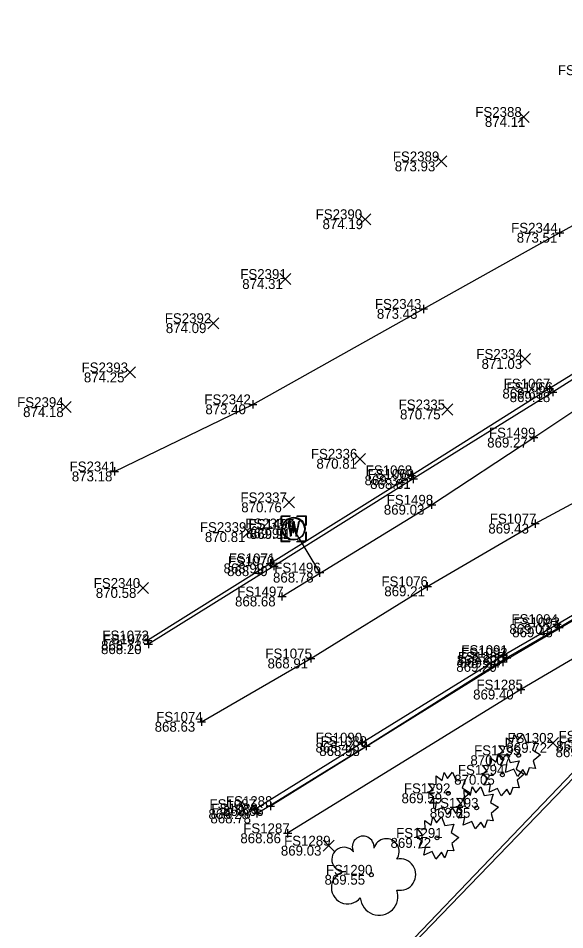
# Model space of a CAD drawing. Extents: x 1479420 to 1479833, y 379731 to 380103.
# Drawn here: x 1479419.6 to 1479485.7, y 379796.9 to 379907.1 of the extents above; entities that cross this region are included whole.
import ezdxf

# ---------------------------------------------------------------- set-up
doc = ezdxf.new("R2010")
doc.units = 0
for name, color, linetype in [('PV_X_COP', 7, 'Continuous'), ('PV_X_Curb', 7, 'Continuous'), ('PV_X_Walk', 7, 'Continuous'), ('SV_X_Break_Lines', 7, 'Continuous'), ('SV_X_Random_Point', 7, 'Continuous'), ('SV_X_Shot_Marker', 7, 'Continuous'), ('SV_X_Text_Elevation', 7, 'Continuous'), ('SV_X_Text_Name', 7, 'Continuous'), ('UT_X_Water', 7, 'Continuous'), ('UT_X_Water_Cells', 7, 'Continuous'), ('VG_X_Cells', 7, 'Continuous')]:
    doc.layers.add(name, color=color, linetype=linetype)

msp = doc.modelspace()

# ---------------------------------------------------------------- linework, layer by layer
at = {"layer": 'PV_X_COP'}
msp.add_lwpolyline([(1479441.79, 379822.02), (1479455, 379829.68), (1479469.1, 379838.41), (1479482.14, 379846), (1479493.53, 379852.15), (1479505.23, 379858.04), (1479517.8, 379863.73), (1479530.74, 379869.52), (1479544.65, 379875.38), (1479558.93, 379881.46), (1479574.04, 379887.9), (1479589.2, 379894.6), (1479596.44, 379897.36)], dxfattribs=at)
at = {"layer": 'PV_X_Curb'}
for points in [[(1479566.95, 379909.06), (1479563.85, 379905.52), (1479559.69, 379902.15), (1479555.35, 379899.31), (1479545.42, 379894.6), (1479534.9, 379889.66), (1479522.4, 379883.6), (1479509.98, 379877.66), (1479501.21, 379872.62), (1479492.67, 379867.77), (1479483.86, 379862.33), (1479467.17, 379851.84), (1479450.13, 379841.19), (1479435.27, 379831.86)], [(1479567.17, 379908.64), (1479563.94, 379905), (1479559.95, 379901.76), (1479555.61, 379898.81), (1479545.71, 379894.1), (1479535.14, 379889.11), (1479522.8, 379883.21), (1479510.32, 379877.21), (1479501.52, 379872.22), (1479492.73, 379867.27), (1479484.26, 379861.9), (1479467.4, 379851.4), (1479450.55, 379840.85), (1479435.37, 379831.41)], [(1479448.26, 379811.45), (1479461.22, 379819.5), (1479478.3, 379830.09), (1479484.79, 379833.84), (1479492.12, 379838.16), (1479500.7, 379842.97), (1479508.92, 379847.12), (1479516.09, 379849.63), (1479529.03, 379853.07), (1479547.64, 379857.82), (1479566.74, 379862.68), (1479585.84, 379867.63), (1479595.94, 379870.21)], [(1479448.5, 379810.93), (1479461.7, 379819.08), (1479478.68, 379829.77), (1479485.03, 379833.45), (1479492.45, 379837.86), (1479500.92, 379842.63), (1479509.09, 379846.69), (1479516.12, 379849.21), (1479529.31, 379852.68), (1479547.62, 379857.33), (1479567.19, 379862.3), (1479585.96, 379867.1), (1479596.07, 379869.8)], [(1479601.32, 379856.89), (1479590.52, 379858.04), (1479580.72, 379858.06), (1479571.15, 379856.79), (1479561.29, 379853.75), (1479553.09, 379850.7), (1479544.73, 379845.63), (1479537.42, 379839.85), (1479530.35, 379833.14), (1479518.15, 379820.18), (1479506.75, 379808.8), (1479505.04, 379808.13), (1479502.74, 379808.99), (1479490.36, 379819.72), (1479452.91, 379780.6)], [(1479601.35, 379856.37), (1479590.36, 379857.44), (1479580.92, 379857.48), (1479571.06, 379856.27), (1479561.56, 379853.27), (1479553.28, 379850.19), (1479545.2, 379845.23), (1479537.87, 379839.39), (1479530.79, 379832.84), (1479518.52, 379819.83), (1479508.59, 379809.05), (1479504.77, 379807.6), (1479502.38, 379808.45), (1479490.37, 379818.94), (1479453.51, 379780.8)]]:
    msp.add_lwpolyline(points, dxfattribs=at)
at = {"layer": 'PV_X_Walk'}
for points in [[(1479600.53, 379870.64), (1479580.73, 379865.6), (1479561.55, 379860.77), (1479542.71, 379855.92), (1479519.92, 379850.15), (1479513.47, 379848.18), (1479509.19, 379846.57), (1479504.25, 379844.07), (1479496.36, 379839.93), (1479478.25, 379829.27), (1479450.13, 379811.82)], [(1479601.31, 379866.86), (1479581.55, 379861.92), (1479562.5, 379857.02), (1479543.7, 379852.15), (1479520.94, 379846.41), (1479515.03, 379844.63), (1479510.75, 379842.94), (1479506.29, 379840.86), (1479498.37, 379836.48), (1479480.41, 379825.92), (1479452.2, 379808.53)]]:
    msp.add_lwpolyline(points, dxfattribs=at)
at = {"layer": 'SV_X_Break_Lines'}
msp.add_lwpolyline([(1479431.27, 379852.31), (1479448, 379860.43), (1479468.63, 379871.98), (1479485.1, 379881.19), (1479495.91, 379887.13), (1479497.06, 379892.33), (1479500.76, 379896.46), (1479508.23, 379894.89), (1479514.09, 379896.92), (1479525.63, 379901.77), (1479534.39, 379905.65), (1479543.52, 379912.47)], dxfattribs=at)
at = {"layer": 'SV_X_Random_Point'}
for p, q in [((1479480.1, 379894.54), (1479481.43, 379895.87)), ((1479480.1, 379895.87), (1479481.43, 379894.54)), ((1479470.13, 379889.16), (1479471.47, 379890.49)), ((1479470.13, 379890.49), (1479471.47, 379889.16)), ((1479460.91, 379882.16), (1479462.25, 379883.49)), ((1479460.91, 379883.49), (1479462.25, 379882.16)), ((1479451.25, 379874.92), (1479452.58, 379876.26)), ((1479451.25, 379876.26), (1479452.58, 379874.92)), ((1479442.55, 379869.58), (1479443.88, 379870.91)), ((1479442.55, 379870.91), (1479443.88, 379869.58)), ((1479480.23, 379865.25), (1479481.57, 379866.58)), ((1479480.23, 379866.58), (1479481.57, 379865.25)), ((1479432.5, 379863.63), (1479433.83, 379864.96)), ((1479432.5, 379864.96), (1479433.83, 379863.63)), ((1479424.7, 379859.43), (1479426.03, 379860.76)), ((1479424.7, 379860.76), (1479426.03, 379859.43)), ((1479470.84, 379859.14), (1479472.17, 379860.48)), ((1479470.84, 379860.48), (1479472.17, 379859.14)), ((1479460.31, 379853.17), (1479461.64, 379854.5)), ((1479460.31, 379854.5), (1479461.64, 379853.17)), ((1479451.71, 379847.91), (1479453.04, 379849.24)), ((1479451.71, 379849.24), (1479453.04, 379847.91)), ((1479446.82, 379844.3), (1479448.15, 379845.64)), ((1479446.82, 379845.64), (1479448.15, 379844.3)), ((1479434.07, 379837.54), (1479435.4, 379838.88)), ((1479434.07, 379838.88), (1479435.4, 379837.54)), ((1479483.63, 379818.8), (1479484.96, 379820.14)), ((1479483.63, 379820.14), (1479484.96, 379818.8)), ((1479456.49, 379806.36), (1479457.83, 379807.7)), ((1479456.49, 379807.7), (1479457.83, 379806.36))]:
    msp.add_line(p, q, dxfattribs=at)
at = {"layer": 'SV_X_Shot_Marker'}
for p, q in [((1479484.6, 379881.19), (1479485.6, 379881.19)), ((1479485.1, 379881.69), (1479485.1, 379880.69)), ((1479485.1, 379881.19), (1479485.1, 379881.19)), ((1479468.63, 379872.48), (1479468.63, 379871.48)), ((1479468.13, 379871.98), (1479469.13, 379871.98)), ((1479468.63, 379871.98), (1479468.63, 379871.98)), ((1479483.36, 379862.33), (1479484.36, 379862.33)), ((1479483.86, 379862.83), (1479483.86, 379861.83)), ((1479483.86, 379862.33), (1479483.86, 379862.33)), ((1479484.26, 379862.4), (1479484.26, 379861.4)), ((1479483.76, 379861.9), (1479484.76, 379861.9)), ((1479484.26, 379861.9), (1479484.26, 379861.9)), ((1479447.5, 379860.43), (1479448.5, 379860.43)), ((1479448, 379860.93), (1479448, 379859.93)), ((1479448, 379860.43), (1479448, 379860.43)), ((1479481.98, 379856.9), (1479481.98, 379855.9)), ((1479481.48, 379856.4), (1479482.48, 379856.4)), ((1479481.98, 379856.4), (1479481.98, 379856.4)), ((1479430.77, 379852.31), (1479431.77, 379852.31)), ((1479431.27, 379852.81), (1479431.27, 379851.81)), ((1479431.27, 379852.31), (1479431.27, 379852.31)), ((1479467.17, 379852.34), (1479467.17, 379851.34)), ((1479466.67, 379851.84), (1479467.67, 379851.84)), ((1479466.9, 379851.4), (1479467.9, 379851.4)), ((1479467.17, 379851.84), (1479467.17, 379851.84)), ((1479467.4, 379851.9), (1479467.4, 379850.9)), ((1479467.4, 379851.4), (1479467.4, 379851.4)), ((1479469.11, 379848.28), (1479470.11, 379848.28)), ((1479469.61, 379848.78), (1479469.61, 379847.78)), ((1479469.61, 379848.28), (1479469.61, 379848.28)), ((1479452.88, 379845.86), (1479452.88, 379844.86)), ((1479481.64, 379846), (1479482.64, 379846)), ((1479482.14, 379846.5), (1479482.14, 379845.5)), ((1479482.14, 379846), (1479482.14, 379846)), ((1479452.38, 379845.36), (1479453.38, 379845.36)), ((1479452.88, 379845.36), (1479452.88, 379845.36)), ((1479449.63, 379841.19), (1479450.63, 379841.19)), ((1479450.13, 379841.69), (1479450.13, 379840.69)), ((1479450.13, 379841.19), (1479450.13, 379841.19)), ((1479450.55, 379841.35), (1479450.55, 379840.35)), ((1479450.05, 379840.85), (1479451.05, 379840.85)), ((1479450.55, 379840.85), (1479450.55, 379840.85)), ((1479455.57, 379840.07), (1479456.57, 379840.07)), ((1479456.07, 379840.57), (1479456.07, 379839.57)), ((1479456.07, 379840.07), (1479456.07, 379840.07)), ((1479469.1, 379838.91), (1479469.1, 379837.91)), ((1479468.6, 379838.41), (1479469.6, 379838.41)), ((1479469.1, 379838.41), (1479469.1, 379838.41)), ((1479451.02, 379837.18), (1479452.02, 379837.18)), ((1479451.52, 379837.68), (1479451.52, 379836.68)), ((1479451.52, 379837.18), (1479451.52, 379837.18)), ((1479484.29, 379833.84), (1479485.29, 379833.84)), ((1479484.53, 379833.45), (1479485.53, 379833.45)), ((1479484.79, 379834.34), (1479484.79, 379833.34)), ((1479484.79, 379833.84), (1479484.79, 379833.84)), ((1479485.03, 379833.95), (1479485.03, 379832.95)), ((1479485.03, 379833.45), (1479485.03, 379833.45)), ((1479435.27, 379832.36), (1479435.27, 379831.36)), ((1479434.77, 379831.86), (1479435.77, 379831.86)), ((1479434.87, 379831.41), (1479435.87, 379831.41)), ((1479435.27, 379831.86), (1479435.27, 379831.86)), ((1479435.37, 379831.91), (1479435.37, 379830.91)), ((1479435.37, 379831.41), (1479435.37, 379831.41)), ((1479455, 379830.18), (1479455, 379829.18)), ((1479477.8, 379830.09), (1479478.8, 379830.09)), ((1479478.3, 379830.59), (1479478.3, 379829.59)), ((1479478.3, 379830.09), (1479478.3, 379830.09)), ((1479478.68, 379830.27), (1479478.68, 379829.27)), ((1479454.5, 379829.68), (1479455.5, 379829.68)), ((1479455, 379829.68), (1479455, 379829.68)), ((1479477.75, 379829.27), (1479478.75, 379829.27)), ((1479478.18, 379829.77), (1479479.18, 379829.77)), ((1479478.25, 379829.77), (1479478.25, 379828.77)), ((1479478.25, 379829.27), (1479478.25, 379829.27)), ((1479478.68, 379829.77), (1479478.68, 379829.77)), ((1479479.91, 379825.92), (1479480.91, 379825.92)), ((1479480.41, 379826.42), (1479480.41, 379825.42)), ((1479480.41, 379825.92), (1479480.41, 379825.92)), ((1479441.79, 379822.52), (1479441.79, 379821.52)), ((1479441.29, 379822.02), (1479442.29, 379822.02)), ((1479441.79, 379822.02), (1479441.79, 379822.02)), ((1479460.72, 379819.5), (1479461.72, 379819.5)), ((1479461.2, 379819.08), (1479462.2, 379819.08)), ((1479461.22, 379820), (1479461.22, 379819)), ((1479461.22, 379819.5), (1479461.22, 379819.5)), ((1479461.7, 379819.58), (1479461.7, 379818.58)), ((1479461.7, 379819.08), (1479461.7, 379819.08)), ((1479447.76, 379811.45), (1479448.76, 379811.45)), ((1479448.26, 379811.95), (1479448.26, 379810.95)), ((1479448.26, 379811.45), (1479448.26, 379811.45)), ((1479448.5, 379811.43), (1479448.5, 379810.43)), ((1479449.63, 379811.82), (1479450.63, 379811.82)), ((1479450.13, 379812.32), (1479450.13, 379811.32)), ((1479450.13, 379811.82), (1479450.13, 379811.82)), ((1479448, 379810.93), (1479449, 379810.93)), ((1479448.5, 379810.93), (1479448.5, 379810.93)), ((1479451.7, 379808.53), (1479452.7, 379808.53)), ((1479452.2, 379809.03), (1479452.2, 379808.03)), ((1479452.2, 379808.53), (1479452.2, 379808.53))]:
    msp.add_line(p, q, dxfattribs=at)
at = {"layer": 'UT_X_Water'}
msp.add_line((1479452.88, 379845.36), (1479456.07, 379840.07), dxfattribs=at)
msp.add_lwpolyline([(1479451.52, 379837.18), (1479469.61, 379848.28), (1479481.98, 379856.4), (1479496.24, 379865.93), (1479520, 379881.31), (1479538.56, 379893), (1479553.44, 379903.41), (1479554.94, 379904.33), (1479564.84, 379911.31), (1479573.24, 379917), (1479582.4, 379926.47), (1479585.51, 379929.79), (1479589.65, 379934.74), (1479591.4, 379936.45), (1479593.77, 379939.33)], dxfattribs=at)
at = {"layer": 'UT_X_Water_Cells'}
for p, q in [((1479452.89, 379845.34), (1479452.89, 379845.34)), ((1479452.97, 379845.41), (1479452.97, 379845.41))]:
    msp.add_line(p, q, dxfattribs=at)
for points in [[(1479452.49, 379846.84), (1479451.39, 379846.84), (1479451.39, 379845.74)], [(1479452.57, 379846.91), (1479451.47, 379846.91), (1479451.47, 379845.81)], [(1479454.39, 379845.74), (1479454.39, 379846.84), (1479453.29, 379846.84)], [(1479454.47, 379845.81), (1479454.47, 379846.91), (1479453.37, 379846.91)], [(1479452.23, 379846.24), (1479452.56, 379844.44), (1479452.89, 379846.24), (1479453.23, 379844.44), (1479453.56, 379846.24)], [(1479452.3, 379846.31), (1479452.64, 379844.51), (1479452.97, 379846.31), (1479453.3, 379844.51), (1479453.64, 379846.31)], [(1479451.39, 379844.94), (1479451.39, 379843.84), (1479452.49, 379843.84)], [(1479451.47, 379845.01), (1479451.47, 379843.91), (1479452.57, 379843.91)], [(1479453.29, 379843.84), (1479454.39, 379843.84), (1479454.39, 379844.94)], [(1479453.37, 379843.91), (1479454.47, 379843.91), (1479454.47, 379845.01)]]:
    msp.add_lwpolyline(points, dxfattribs=at)
for centre in [(1479452.89, 379845.34), (1479452.97, 379845.41)]:
    msp.add_circle(centre, 1.35, dxfattribs=at)
at = {"layer": 'VG_X_Cells'}
for points in [[(1479480.06, 379819.78), (1479480.66, 379820.51), (1479481.08, 379819.46), (1479482.17, 379819.64), (1479481.83, 379818.63), (1479482.78, 379818.03), (1479481.92, 379817.3), (1479482.17, 379816.38), (1479481.42, 379816.45), (1479481.09, 379815.54), (1479480.66, 379816.23), (1479479.99, 379815.41), (1479479.56, 379816.3), (1479478.54, 379815.87), (1479478.73, 379816.81), (1479477.92, 379816.73), (1479478.39, 379817.52), (1479477.62, 379818.09), (1479478.36, 379818.35), (1479477.75, 379819.15), (1479478.69, 379819.04), (1479478.66, 379820.08), (1479479.41, 379819.51), (1479479.62, 379820.5), (1479480.06, 379819.78)], [(1479478.09, 379817.42), (1479478.7, 379818.15), (1479479.11, 379817.1), (1479480.2, 379817.28), (1479479.86, 379816.27), (1479480.81, 379815.67), (1479479.95, 379814.94), (1479480.2, 379814.02), (1479479.45, 379814.09), (1479479.12, 379813.18), (1479478.7, 379813.87), (1479478.02, 379813.05), (1479477.59, 379813.94), (1479476.57, 379813.51), (1479476.76, 379814.45), (1479475.95, 379814.37), (1479476.42, 379815.16), (1479475.65, 379815.73), (1479476.39, 379815.99), (1479475.79, 379816.79), (1479476.72, 379816.68), (1479476.69, 379817.72), (1479477.44, 379817.15), (1479477.65, 379818.14), (1479478.09, 379817.42)], [(1479471.56, 379815.18), (1479472.16, 379815.92), (1479472.58, 379814.86), (1479473.67, 379815.04), (1479473.33, 379814.03), (1479474.28, 379813.44), (1479473.42, 379812.7), (1479473.67, 379811.79), (1479472.92, 379811.86), (1479472.59, 379810.94), (1479472.16, 379811.63), (1479471.49, 379810.82), (1479471.06, 379811.7), (1479470.04, 379811.27), (1479470.23, 379812.22), (1479469.42, 379812.13), (1479469.89, 379812.92), (1479469.12, 379813.49), (1479469.86, 379813.75), (1479469.25, 379814.56), (1479470.19, 379814.45), (1479470.16, 379815.49), (1479470.91, 379814.92), (1479471.12, 379815.9), (1479471.56, 379815.18)], [(1479474.97, 379813.42), (1479475.58, 379814.16), (1479475.99, 379813.1), (1479477.08, 379813.28), (1479476.74, 379812.27), (1479477.69, 379811.68), (1479476.83, 379810.94), (1479477.08, 379810.03), (1479476.33, 379810.1), (1479476, 379809.18), (1479475.58, 379809.87), (1479474.9, 379809.06), (1479474.47, 379809.94), (1479473.45, 379809.51), (1479473.64, 379810.46), (1479472.83, 379810.37), (1479473.3, 379811.16), (1479472.53, 379811.73), (1479473.27, 379811.99), (1479472.67, 379812.8), (1479473.6, 379812.69), (1479473.57, 379813.73), (1479474.32, 379813.16), (1479474.53, 379814.14), (1479474.97, 379813.42)], [(1479470.2, 379809.78), (1479470.8, 379810.52), (1479471.22, 379809.47), (1479472.31, 379809.65), (1479471.97, 379808.63), (1479472.92, 379808.04), (1479472.06, 379807.3), (1479472.31, 379806.39), (1479471.56, 379806.46), (1479471.23, 379805.55), (1479470.8, 379806.24), (1479470.13, 379805.42), (1479469.7, 379806.31), (1479468.68, 379805.88), (1479468.87, 379806.82), (1479468.06, 379806.74), (1479468.53, 379807.53), (1479467.76, 379808.09), (1479468.5, 379808.36), (1479467.89, 379809.16), (1479468.83, 379809.05), (1479468.8, 379810.09), (1479469.55, 379809.52), (1479469.76, 379810.51), (1479470.2, 379809.78)]]:
    msp.add_lwpolyline(points, dxfattribs=at)
for centre, radius in [((1479480.14, 379817.97), 0.23), ((1479478.18, 379815.61), 0.23), ((1479471.64, 379813.37), 0.23), ((1479475.06, 379811.61), 0.23), ((1479470.28, 379807.98), 0.23), ((1479462.33, 379803.51), 0.24)]:
    msp.add_circle(centre, radius, dxfattribs=at)
for centre, radius, start, end in [((1479461.34, 379806.87), 1.32, 354.0047, 205.9741), ((1479464.15, 379806.33), 1.55, 323.83, 165.0376), ((1479459.02, 379805.37), 1.47, 39.0625, 279.5412), ((1479465.79, 379803.54), 1.91, 259.1453, 101.4596), ((1479459.47, 379801.96), 1.97, 96.1722, 320.5737), ((1479463.27, 379800.9), 2.28, 184.9476, 19.4572)]:
    msp.add_arc(centre, radius, start, end, dxfattribs=at)

# ---------------------------------------------------------------- texts
at = {"layer": 'SV_X_Text_Elevation'}
for s, p in [('874.11', (1479476.06, 379894)), ('873.93', (1479465.16, 379888.62)), ('874.19', (1479456.43, 379881.63)), ('873.51', (1479479.91, 379879.99)), ('874.31', (1479446.72, 379874.39)), ('873.43', (1479463, 379870.78)), ('874.09', (1479437.48, 379869.05)), ('871.03', (1479475.66, 379864.72)), ('874.25', (1479427.57, 379863.09)), ('869.65', (1479478.18, 379861.13)), ('869.18', (1479479.06, 379860.7)), ('874.18', (1479420.22, 379858.89)), ('873.40', (1479442.26, 379859.23)), ('870.75', (1479465.8, 379858.61)), ('869.27', (1479476.34, 379855.2)), ('870.81', (1479455.69, 379852.64)), ('873.18', (1479426.11, 379851.11)), ('869.34', (1479461.51, 379850.64)), ('868.81', (1479462.19, 379850.2)), ('870.76', (1479446.6, 379847.37)), ('869.03', (1479463.84, 379847.08)), ('869.43', (1479476.48, 379844.8)), ('870.81', (1479442.2, 379843.77)), ('869.90', (1479447.19, 379844.21)), ('869.91', (1479447.63, 379844.16)), ('869.91', (1479447.65, 379844.14)), ('868.99', (1479444.46, 379839.99)), ('868.49', (1479444.89, 379839.65)), ('868.78', (1479450.44, 379838.87)), ('870.58', (1479429.01, 379837.01)), ('869.21', (1479463.9, 379837.21)), ('868.68', (1479445.85, 379835.98)), ('869.02', (1479479.02, 379832.64)), ('869.48', (1479479.36, 379832.25)), ('868.20', (1479429.64, 379830.21)), ('868.73', (1479429.65, 379830.66)), ('868.82', (1479472.67, 379828.89)), ('868.91', (1479449.78, 379828.48)), ('869.29', (1479472.6, 379828.07)), ('869.34', (1479473.01, 379828.57)), ('869.40', (1479474.64, 379824.72)), ('868.63', (1479436.13, 379820.82)), ('868.44', (1479455.58, 379818.3)), ('868.98', (1479456.03, 379817.88)), ('869.72', (1479478.67, 379818.27)), ('869.88', (1479484.69, 379818.52)), ('870.07', (1479474.31, 379816.77)), ('869.36', (1479484.61, 379817.74)), ('870.05', (1479472.35, 379814.41)), ('869.59', (1479465.98, 379812.17)), ('868.28', (1479442.63, 379810.25)), ('868.66', (1479444.39, 379810.62)), ('869.85', (1479469.4, 379810.41)), ('868.78', (1479442.87, 379809.73)), ('868.86', (1479446.49, 379807.33)), ('869.03', (1479451.39, 379805.83)), ('869.72', (1479464.65, 379806.77)), ('869.55', (1479456.67, 379802.31))]:
    msp.add_text(s, height=1.2, dxfattribs=at).set_placement(p)
at = {"layer": 'SV_X_Text_Name'}
for s, p in [('FS2387', (1479484.89, 379900.26)), ('FS2388', (1479474.9, 379895.2)), ('FS2389', (1479464.93, 379889.82)), ('FS2390', (1479455.6, 379882.83)), ('FS2344', (1479479.24, 379881.19)), ('FS2391', (1479446.48, 379875.59)), ('FS2343', (1479462.76, 379871.98)), ('FS2392', (1479437.35, 379870.25)), ('FS2334', (1479475.03, 379865.92)), ('FS2393', (1479427.29, 379864.29)), ('FS1067', (1479478.34, 379862.33)), ('FS1066', (1479478.67, 379861.9)), ('FS2394', (1479419.5, 379860.09)), ('FS2342', (1479442.14, 379860.43)), ('FS2335', (1479465.63, 379859.81)), ('FS1499', (1479476.56, 379856.4)), ('FS2336', (1479455.02, 379853.84)), ('FS2341', (1479425.84, 379852.31)), ('FS1068', (1479461.65, 379851.84)), ('FS1069', (1479461.87, 379851.4)), ('FS2337', (1479446.5, 379848.57)), ('FS1498', (1479464.19, 379848.28)), ('FS2338', (1479447.08, 379845.41)), ('FS1077', (1479476.66, 379846)), ('FS2339', (1479441.6, 379844.97)), ('FS1495', (1479447.46, 379845.36)), ('FS1494', (1479447.49, 379845.34)), ('FS1071', (1479445.09, 379841.19)), ('FS1070', (1479444.97, 379840.85)), ('FS1496', (1479450.59, 379840.07)), ('FS2340', (1479428.76, 379838.21)), ('FS1076', (1479463.55, 379838.41)), ('FS1497', (1479446.11, 379837.18)), ('FS1094', (1479479.28, 379833.84)), ('FS1093', (1479479.52, 379833.45)), ('FS1072', (1479429.8, 379831.86)), ('FS1073', (1479429.89, 379831.41)), ('FS1091', (1479473.22, 379830.09)), ('FS1075', (1479449.52, 379829.68)), ('FS1286', (1479472.81, 379829.27)), ('FS1092', (1479473.18, 379829.77)), ('FS1285', (1479475.04, 379825.92)), ('FS1074', (1479436.32, 379822.02)), ('FS1090', (1479455.6, 379819.5)), ('FS1089', (1479456.19, 379819.08)), ('FS1302', (1479478.79, 379819.47)), ('FS1478', (1479484.97, 379819.72)), ('FS1479', (1479484.98, 379818.94)), ('FS1295', (1479474.76, 379817.97)), ('FS1294', (1479472.8, 379815.61)), ('FS1292', (1479466.27, 379813.37)), ('FS1087', (1479442.76, 379811.45)), ('FS1288', (1479444.75, 379811.82)), ('FS1293', (1479469.67, 379811.61)), ('FS1088', (1479442.99, 379810.93)), ('FS1287', (1479446.84, 379808.53)), ('FS1291', (1479465.33, 379807.97)), ('FS1289', (1479451.78, 379807.03)), ('FS1290', (1479456.84, 379803.51))]:
    msp.add_text(s, height=1.2, dxfattribs=at).set_placement(p)

doc.saveas('drawing.dxf')
